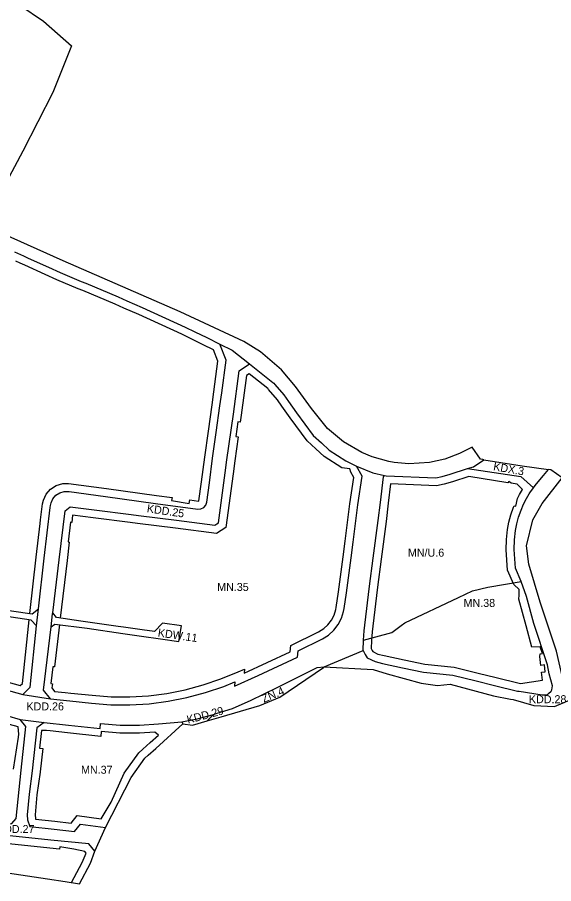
# Model space of a CAD drawing. Extents: x 7414808 to 7417449, y 5544732 to 5546764.
# Drawn here: x 7416233 to 7416568, y 5545519 to 5546060 of the extents above; entities that cross this region are included whole.
import ezdxf

# ---------------------------------------------------------------- set-up
doc = ezdxf.new("R2010")
doc.units = 0
for name, color, linetype in [('LIN_Linie Rozgraniczajace', 7, 'Continuous'), ('LIN_nieprzekraczale linie zabudowy', 7, 'Continuous'), ('TXT_Oznaczenia Przeznaczenia', 7, 'Continuous')]:
    doc.layers.add(name, color=color, linetype=linetype)

msp = doc.modelspace()

# ---------------------------------------------------------------- linework, layer by layer
at = {"layer": 'LIN_Linie Rozgraniczajace'}
for p, q in [((7416424.39, 5545654.6), (7416448.61, 5545664.88)), ((7416351.14, 5545620.75), (7416355.09, 5545624.78)), ((7416335.28, 5545620.28), (7416336.08, 5545618.97))]:
    msp.add_line(p, q, dxfattribs=at)
for points in [[(7416031.71, 5546182.56), (7416063.73, 5546184.03), (7416096.6, 5546180.73), (7416104.92, 5546178.85), (7416103.96, 5546121.51), (7416130.11, 5546113.16), (7416156.81, 5546103.29), (7416174.89, 5546095.8), (7416191.75, 5546088.18), (7416192.64, 5546087.68), (7416211.01, 5546078.61), (7416234.18, 5546068.04), (7416248.86, 5546058.11), (7416257.56, 5546050.25), (7416266.33, 5546042.67), (7416254.64, 5546013.41), (7416236.06, 5545976.82), (7416225.54, 5545957.13), (7416215, 5545936.65)], [(7416524.05, 5545784), (7416523.57, 5545784.08), (7416521.98, 5545784.32), (7416516.88, 5545791.94), (7416508.94, 5545787.78), (7416499.67, 5545784.33), (7416490.17, 5545782.33), (7416477.23, 5545781.39), (7416468.1, 5545782.16), (7416464.65, 5545782.87), (7416454.4, 5545785.72), (7416447.92, 5545788.49), (7416436.37, 5545795.2), (7416426.46, 5545803.6), (7416416.42, 5545816.04), (7416406.45, 5545829.85), (7416397.68, 5545840.12), (7416384.46, 5545851.46), (7416374.19, 5545857.96), (7416334.28, 5545876.3), (7416261.17, 5545908.31), (7416212.34, 5545930.15), (7416215, 5545936.65)], [(7416230.76, 5545913.95), (7416236.34, 5545911.37), (7416239.31, 5545910.01), (7416252.01, 5545904.27), (7416259.34, 5545901.01), (7416272.52, 5545895.39), (7416275.31, 5545894.24), (7416295.55, 5545885.7), (7416301.08, 5545883.36), (7416310.55, 5545879.2), (7416337.49, 5545866.9), (7416343.44, 5545863.96), (7416350.96, 5545860.26), (7416359.11, 5545856.23)], [(7416245.78, 5545690.76), (7416249.25, 5545722.57), (7416253.11, 5545754.06), (7416253.28, 5545755.42), (7416253.62, 5545757.08), (7416254.81, 5545759.64), (7416256.66, 5545761.77), (7416259.03, 5545763.29), (7416261.73, 5545764.1), (7416264.55, 5545764.12), (7416264.97, 5545764.06), (7416287.65, 5545760.96), (7416318.95, 5545756.69), (7416345.27, 5545753.1), (7416347.25, 5545753.23), (7416349.03, 5545754.12), (7416350.32, 5545755.64), (7416350.9, 5545757.38), (7416352.56, 5545769.6), (7416354.63, 5545784.88), (7416356.89, 5545801.09), (7416359.18, 5545817.69), (7416360.27, 5545825.72), (7416363.02, 5545846.18), (7416359.11, 5545856.23)], [(7416359.11, 5545856.23), (7416366.75, 5545852.45), (7416377.71, 5545843.97)], [(7416254.67, 5545688.24), (7416258.65, 5545721.53), (7416262.35, 5545752.16), (7416265.59, 5545754.54), (7416280.56, 5545752.65), (7416303.62, 5545749.75), (7416308.31, 5545749.17), (7416332.08, 5545746.25), (7416355.93, 5545743.14), (7416357.2, 5545743.92), (7416358.24, 5545744.57), (7416362.49, 5545775.86), (7416363.58, 5545783.91), (7416367.56, 5545812.43), (7416371.21, 5545839.57), (7416377.71, 5545843.97)], [(7416377.71, 5545843.97), (7416392.24, 5545832.32), (7416392.94, 5545831.73), (7416393.45, 5545831.09), (7416399.02, 5545824.52), (7416401.98, 5545820.32), (7416407.12, 5545813.21), (7416417.48, 5545799.22), (7416422.59, 5545794.52), (7416427.42, 5545789.98), (7416437.91, 5545783.23), (7416444.59, 5545779.97)], [(7416253.19, 5545634.5), (7416265.42, 5545633.26), (7416278.96, 5545631.81), (7416290.92, 5545630.93), (7416302.92, 5545630.85), (7416314.9, 5545631.57), (7416326.8, 5545633.08), (7416338.57, 5545635.39), (7416350.17, 5545638.47), (7416361.53, 5545642.32), (7416368.56, 5545645.24), (7416368.22, 5545642.44), (7416383.08, 5545649.24), (7416407.61, 5545660.61), (7416408.17, 5545664.57), (7416423.24, 5545672.11), (7416427.04, 5545674.45), (7416430.36, 5545677.44), (7416433.1, 5545680.97), (7416435.17, 5545684.93), (7416436.5, 5545689.2), (7416436.81, 5545690.97), (7416438.2, 5545700.81), (7416441.09, 5545722.61), (7416442.43, 5545732.55), (7416445.38, 5545755.73), (7416448.04, 5545773.73), (7416444.59, 5545779.97)], [(7416444.59, 5545779.97), (7416454.73, 5545775.84), (7416461.96, 5545774.24)], [(7416513.96, 5545778.45), (7416517.6, 5545779.62), (7416524.05, 5545784)], [(7416524.05, 5545784), (7416548, 5545780.16), (7416564.52, 5545777.89)], [(7416424.39, 5545654.6), (7416454.9, 5545652.86), (7416463.65, 5545650.29), (7416484.93, 5545644.42), (7416495.09, 5545642.89), (7416503.16, 5545643.72), (7416530.12, 5545636.37), (7416540.79, 5545634.34), (7416542.45, 5545634.25), (7416555.42, 5545630.44), (7416568.36, 5545629.89), (7416580.65, 5545635.01), (7416573.56, 5545647.14), (7416569.62, 5545664.38), (7416559.28, 5545694.98), (7416552.22, 5545718.82), (7416550.7, 5545730.15), (7416554.74, 5545746.53), (7416560.62, 5545756.65), (7416573.12, 5545772.65), (7416565.95, 5545777.69), (7416564.52, 5545777.89)], [(7416448.98, 5545671.24), (7416449.33, 5545677.01), (7416449.76, 5545680.63), (7416452.68, 5545705.09), (7416454.99, 5545722.42), (7416458.06, 5545745.97), (7416459.46, 5545757.34), (7416461.35, 5545773.22), (7416461.96, 5545774.24)], [(7416461.96, 5545774.24), (7416463.1, 5545773.96), (7416494.16, 5545772.71), (7416498.15, 5545773.57), (7416503.05, 5545774.93), (7416513.96, 5545778.45)], [(7416513.96, 5545778.45), (7416547.18, 5545773.43), (7416555.17, 5545766.51)], [(7416555.17, 5545766.51), (7416555.64, 5545767.14), (7416557.01, 5545768.85), (7416561.42, 5545774.15), (7416564.52, 5545777.89)], [(7416547.43, 5545707.96), (7416543.82, 5545716.22), (7416543.17, 5545727.88), (7416543.21, 5545733.84), (7416543.84, 5545739.76), (7416544.65, 5545743.94), (7416545.74, 5545748.01), (7416547.34, 5545752.57), (7416548.9, 5545756.15), (7416550.8, 5545759.83), (7416552.48, 5545762.65), (7416553.29, 5545763.83), (7416554.7, 5545765.89), (7416555.17, 5545766.51)], [(7416244.61, 5545680.15), (7416241.27, 5545683.73), (7416228.65, 5545685.63), (7416216.78, 5545687.41), (7416205.02, 5545689.19), (7416193.25, 5545690.95), (7416181.49, 5545692.72), (7416169.38, 5545694.4), (7416170.52, 5545704.42), (7416182.37, 5545702.72), (7416183.62, 5545696.43), (7416193.51, 5545694.94), (7416205.3, 5545693.18), (7416217.13, 5545691.4), (7416228.92, 5545689.63), (7416241.72, 5545687.7), (7416245.78, 5545690.76)], [(7416448.61, 5545664.88), (7416449.99, 5545662.32), (7416451.11, 5545660.24), (7416456.24, 5545657.86), (7416460.77, 5545656.75), (7416473.29, 5545654.04), (7416486.47, 5545651.25), (7416504.75, 5545649.42), (7416519.36, 5545645.87), (7416530.68, 5545642.98), (7416545.13, 5545639.48), (7416546.16, 5545639.29), (7416560.52, 5545636.99), (7416562.29, 5545637), (7416563.81, 5545637.39), (7416564.6, 5545637.84), (7416566.19, 5545639.37), (7416566.62, 5545640.3), (7416566.91, 5545641.49), (7416566.99, 5545642.62), (7416564.99, 5545650.14), (7416563.96, 5545655.81), (7416555.36, 5545681.65), (7416550.79, 5545698.46), (7416547.43, 5545707.96)], [(7416448.98, 5545671.24), (7416466.53, 5545676.06), (7416472.43, 5545680.39), (7416474.65, 5545682.02), (7416508.33, 5545697.81), (7416517.03, 5545702.13), (7416526.7, 5545704.4), (7416547.43, 5545707.96)], [(7416244.61, 5545680.15), (7416245.78, 5545690.76)], [(7416253.64, 5545679.58), (7416254.6, 5545687.71), (7416254.67, 5545688.24)], [(7416253.64, 5545679.58), (7416256.04, 5545681.35), (7416276.28, 5545678.72), (7416298.48, 5545675.45), (7416310.08, 5545673.82), (7416322.05, 5545672.14), (7416333.55, 5545670.48), (7416335.2, 5545680.18), (7416323.29, 5545681.79), (7416318.38, 5545676.59), (7416310.6, 5545677.76), (7416299, 5545679.39), (7416295.66, 5545679.78), (7416272.15, 5545683.2), (7416256.96, 5545685.42), (7416254.67, 5545688.24)], [(7416235.89, 5545637.3), (7416240.48, 5545641.98), (7416244.61, 5545680.15)], [(7416253.19, 5545634.5), (7416248.94, 5545640.02), (7416251.18, 5545658.88), (7416253.64, 5545679.58)], [(7416448.61, 5545664.88), (7416448.98, 5545671.24)], [(7416133.31, 5545665.82), (7416141.6, 5545664.19), (7416147.8, 5545662.19), (7416159.98, 5545658.26), (7416178.16, 5545653.24), (7416189.86, 5545650.01), (7416201.52, 5545646.8), (7416213.15, 5545643.58), (7416224.83, 5545640.35), (7416235.89, 5545637.3)], [(7416351.14, 5545620.75), (7416359.87, 5545623.29), (7416384.13, 5545630.36), (7416396.62, 5545635.7), (7416423.98, 5545654.09), (7416424.39, 5545654.6)], [(7416366.98, 5545628.61), (7416378.73, 5545633.77), (7416386.45, 5545637.48), (7416394.96, 5545641.64), (7416416.53, 5545652.41), (7416420.01, 5545654.07), (7416424.39, 5545654.6)], [(7416132.78, 5545649.12), (7416136.35, 5545648.74), (7416147.54, 5545646.03), (7416160.59, 5545642.54), (7416175.9, 5545638.27), (7416188.25, 5545634.64), (7416200.73, 5545631.21), (7416213.14, 5545627.73), (7416219.41, 5545625.95), (7416225.72, 5545624.16), (7416234.33, 5545621.67)], [(7416235.89, 5545637.3), (7416253.19, 5545634.5)], [(7416335.28, 5545620.28), (7416344.9, 5545622.14), (7416355.09, 5545624.78), (7416357.44, 5545625.55), (7416366.98, 5545628.61)], [(7416280.89, 5545539.4), (7416277.26, 5545543.91), (7416253.43, 5545546.19), (7416227.81, 5545548.93), (7416212.54, 5545550.95), (7416191.63, 5545553.73), (7416170.85, 5545556.48), (7416158.95, 5545558.06), (7416144.45, 5545559.95), (7416147.19, 5545569.52), (7416160.31, 5545568.05), (7416165.27, 5545564.36), (7416167.14, 5545564.1), (7416180.3, 5545562.33), (7416192.99, 5545560.63), (7416205.81, 5545558.9), (7416218.8, 5545557.21), (7416227.13, 5545556.4), (7416229.18, 5545556.68), (7416231.92, 5545559.87), (7416235.05, 5545590.12), (7416237.84, 5545617.21), (7416234.33, 5545621.67)], [(7416234.33, 5545621.67), (7416249.24, 5545619.85)], [(7416249.24, 5545619.85), (7416244.8, 5545616.44), (7416241.82, 5545589.53), (7416239.86, 5545575.12), (7416238.76, 5545562.17), (7416238.85, 5545558.9), (7416240.28, 5545554.81), (7416255.51, 5545553.13), (7416268.24, 5545551.72), (7416272.02, 5545556.32), (7416287.71, 5545554.3)], [(7416249.24, 5545619.85), (7416264.47, 5545618.22), (7416284.26, 5545616.11), (7416284.5, 5545619.14), (7416296.82, 5545618.23), (7416308.82, 5545618.15), (7416320.8, 5545618.87), (7416335.28, 5545620.28)], [(7416287.71, 5545554.3), (7416303.61, 5545585.5), (7416312.27, 5545597.51), (7416314.42, 5545599.45), (7416319.01, 5545603.59), (7416336.08, 5545618.97)], [(7416336.08, 5545618.97), (7416342.01, 5545618.1), (7416351.14, 5545620.75)], [(7416280.89, 5545539.4), (7416287.71, 5545554.3)], [(7416138.44, 5545527.72), (7416172.34, 5545530.93), (7416188.69, 5545531.4), (7416209.61, 5545528.27), (7416230.49, 5545525.15), (7416251.4, 5545522.03), (7416262.41, 5545520.38), (7416271.32, 5545519.1), (7416278.32, 5545531.86), (7416280.89, 5545539.4)]]:
    msp.add_lwpolyline(points, dxfattribs=at)
at = {"layer": 'LIN_nieprzekraczale linie zabudowy'}
for points in [[(7416240.43, 5545687.89), (7416244.28, 5545723.15), (7416246.87, 5545744.24), (7416246.99, 5545746.41), (7416248.38, 5545756.45), (7416248.85, 5545758.66), (7416250.57, 5545762.38), (7416253.35, 5545765.58), (7416256.92, 5545767.88), (7416260.99, 5545769.09), (7416264.6, 5545769.16), (7416288.32, 5545765.92), (7416319.62, 5545761.65), (7416329.23, 5545760.34), (7416328.94, 5545758.6), (7416339.92, 5545756.71), (7416340.29, 5545758.83), (7416345.82, 5545758.07), (7416345.97, 5545758.24), (7416347.6, 5545770.28), (7416347.6, 5545770.28), (7416349.67, 5545785.55), (7416351.94, 5545801.78), (7416351.94, 5545801.78), (7416354.23, 5545818.37), (7416354.23, 5545818.36), (7416355.31, 5545826.39), (7416357.89, 5545845.57), (7416355.15, 5545852.61), (7416348.74, 5545855.78), (7416341.23, 5545859.48), (7416335.34, 5545862.38), (7416308.51, 5545874.64), (7416299.1, 5545878.77), (7416293.6, 5545881.09), (7416273.39, 5545889.63), (7416270.59, 5545890.78), (7416257.34, 5545896.43), (7416249.96, 5545899.71), (7416237.24, 5545905.46), (7416234.25, 5545906.83), (7416231.53, 5545908.09)], [(7416440.98, 5545776.17), (7416440.38, 5545778.32), (7416435.45, 5545778.87), (7416424.33, 5545786.02), (7416419.19, 5545790.86), (7416413.74, 5545795.86), (7416403.08, 5545810.26), (7416397.91, 5545817.41), (7416395.06, 5545821.45), (7416389.59, 5545827.91), (7416389.34, 5545828.23), (7416389.06, 5545828.46), (7416377.46, 5545837.76), (7416375.87, 5545836.68), (7416372.51, 5545811.75), (7416371.92, 5545807.49), (7416370.43, 5545807.7), (7416369.21, 5545798.57), (7416370.64, 5545798.36), (7416368.53, 5545783.23), (7416367.44, 5545775.19), (7416362.88, 5545741.58), (7416357.09, 5545737.95), (7416331.45, 5545741.29), (7416307.69, 5545744.21), (7416303, 5545744.79), (7416279.93, 5545747.69), (7416267.04, 5545749.32), (7416266.51, 5545744.87), (7416265.82, 5545744.96), (7416264.23, 5545732.69), (7416265.02, 5545732.58), (7416263.61, 5545720.93), (7416259.33, 5545685.07)], [(7416258.84, 5545680.99), (7416255.69, 5545654.49), (7416254.71, 5545654.61), (7416253.42, 5545644.17), (7416254.45, 5545644.04), (7416254.15, 5545641.45), (7416255.84, 5545639.26), (7416262.36, 5545638.59), (7416265.94, 5545638.23), (7416279.4, 5545636.79), (7416291.12, 5545635.93), (7416302.79, 5545635.85), (7416314.43, 5545636.55), (7416326, 5545638.02), (7416337.45, 5545640.26), (7416348.72, 5545643.26), (7416359.77, 5545647), (7416370.58, 5545651.49), (7416374.56, 5545653.14), (7416374.26, 5545650.7), (7416403.04, 5545664), (7416403.58, 5545667.86), (7416420.8, 5545676.48), (7416424.03, 5545678.47), (7416426.69, 5545680.86), (7416428.88, 5545683.68), (7416430.53, 5545686.85), (7416431.63, 5545690.39), (7416431.87, 5545691.76), (7416433.25, 5545701.49), (7416436.13, 5545723.27), (7416437.47, 5545733.2), (7416440.43, 5545756.41), (7416442.85, 5545772.79), (7416440.98, 5545776.17)], [(7416514.72, 5545773.44), (7416504.48, 5545770.14), (7416499.34, 5545768.72), (7416494.6, 5545767.69), (7416465.86, 5545768.84), (7416464.42, 5545756.75), (7416463.02, 5545745.32), (7416459.95, 5545721.76), (7416457.64, 5545704.46), (7416454.72, 5545680.04), (7416454.73, 5545680.04), (7416454.31, 5545676.56), (7416453.97, 5545670.94), (7416453.68, 5545666), (7416454.39, 5545664.69), (7416454.72, 5545664.08), (7416457.9, 5545662.6), (7416461.89, 5545661.62), (7416474.33, 5545658.93), (7416487.24, 5545656.2), (7416505.59, 5545654.36), (7416520.57, 5545650.72), (7416531.88, 5545647.83), (7416546.18, 5545644.37), (7416547.02, 5545644.22), (7416560.67, 5545646.21), (7416560.12, 5545651.3), (7416562.5, 5545651.51), (7416562.12, 5545655.74), (7416559.69, 5545655.49), (7416559.18, 5545661.14), (7416559.23, 5545662.63), (7416560.82, 5545663.02), (7416559.36, 5545667.05), (7416554.19, 5545666.93), (7416550.58, 5545680.21), (7416546.02, 5545696.97), (7416546.28, 5545699.45), (7416546.09, 5545702.92), (7416542.78, 5545706.13), (7416538.88, 5545715.04), (7416538.17, 5545727.76), (7416538.21, 5545734.12), (7416538.89, 5545740.5), (7416539.78, 5545745.06), (7416540.96, 5545749.48), (7416542.68, 5545754.4), (7416542.99, 5545755.11), (7416544.08, 5545754.88), (7416545.1, 5545759.69), (7416546.43, 5545762.27), (7416548.27, 5545765.34), (7416545, 5545768.7), (7416541.29, 5545769.28), (7416539.81, 5545770.4), (7416539.2, 5545769.61), (7416514.72, 5545773.44)], [(7416214.48, 5545648.4), (7416234.38, 5545642.9), (7416235.7, 5545644.24), (7416240, 5545683.92)], [(7416230.08, 5545590.63), (7416233.27, 5545610.66), (7416233.53, 5545612.5), (7416233.07, 5545617.06), (7416218.04, 5545621.14)], [(7416318.46, 5545613.72), (7416308.96, 5545613.15), (7416296.62, 5545613.23), (7416285.03, 5545614.08), (7416284.84, 5545611.01), (7416263.92, 5545613.36), (7416253.01, 5545614.51), (7416250.82, 5545614.76), (7416247.72, 5545614.73), (7416246.39, 5545603.81), (7416248.41, 5545603.61), (7416246.79, 5545588.98), (7416246.77, 5545588.86), (7416244.83, 5545574.57), (7416243.77, 5545562.03), (7416243.83, 5545559.82), (7416243.96, 5545559.43), (7416256.06, 5545558.1), (7416266.1, 5545556.99), (7416269.91, 5545561.63), (7416284.85, 5545559.71), (7416291.22, 5545570.02), (7416299.33, 5545588.11), (7416308.53, 5545600.87), (7416311.07, 5545603.16), (7416315.66, 5545607.3), (7416320.8, 5545611.94), (7416318.46, 5545613.72)], [(7416266.34, 5545519.82), (7416273.13, 5545532.38), (7416275.47, 5545538.17), (7416274.69, 5545539.13), (7416267.84, 5545540.62), (7416259.15, 5545542.09), (7416258.91, 5545540.64), (7416252.95, 5545541.21), (7416252.9, 5545541.22), (7416227.28, 5545543.96)]]:
    msp.add_lwpolyline(points, dxfattribs=at)

# ---------------------------------------------------------------- texts
at = {"layer": 'TXT_Oznaczenia Przeznaczenia'}
for s, rotation, p in [('KDX.3', 350, (7416529.74, 5545777.5)), ('KDD.25', 351.7183, (7416313.28, 5545751.21)), ('KDW.11', 351.8119, (7416320.13, 5545673.57)), ('ZN.4', 23, (7416386.6, 5545632.03)), ('KDD.29', 15, (7416339.25, 5545619))]:
    msp.add_text(s, height=5, rotation=rotation, dxfattribs=at).set_placement(p)
for s, p in [('MN/U.6', (7416476.68, 5545723.43)), ('MN.35', (7416357.46, 5545702)), ('MN.38', (7416511.47, 5545692.02)), ('KDD.28', (7416552.29, 5545631.86)), ('KDD.26', (7416238.26, 5545627.38)), ('MN.37', (7416272.37, 5545587.79)), ('KDD.27', (7416219.84, 5545550.75))]:
    msp.add_text(s, height=5, dxfattribs=at).set_placement(p)

doc.saveas('drawing.dxf')
